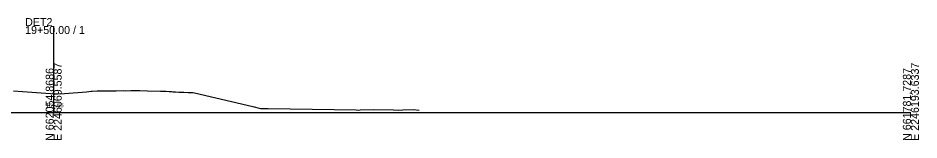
# Model space of a CAD drawing. Extents: x -26 to 603, y -10 to 9526.
# Drawn here: x 287.5 to 602.8, y 2490.3 to 2533.2 of the extents above; entities that cross this region are included whole.
import ezdxf

# ---------------------------------------------------------------- set-up
doc = ezdxf.new("R2010")
doc.units = 0
for name, color, linetype in [('Exist Cross Section Cell', 7, 'Continuous'), ('Exist XS Center Line Elevation Label', 7, 'Continuous'), ('Exist XS Ground Line', 7, 'Continuous')]:
    doc.layers.add(name, color=color, linetype=linetype)

msp = doc.modelspace()

# ---------------------------------------------------------------- linework, layer by layer
at = {"layer": 'Exist Cross Section Cell'}
for p, q in [((300, 2500), (300, 2530.33)), ((0, 2500), (300, 2500)), ((300, 2500), (600, 2500))]:
    msp.add_line(p, q, dxfattribs=at)
at = {"layer": 'Exist XS Ground Line'}
for p, q in [((285.9, 2507.53), (289.13, 2507.37)), ((289.13, 2507.37), (298.91, 2506.61)), ((303.8, 2506.67), (311.48, 2507.28)), ((311.48, 2507.28), (313.11, 2507.44)), ((313.11, 2507.44), (313.51, 2507.49)), ((313.51, 2507.49), (315.26, 2507.55)), ((315.26, 2507.55), (315.68, 2507.56)), ((315.68, 2507.56), (316.33, 2507.57)), ((316.33, 2507.57), (319.12, 2507.59)), ((319.12, 2507.59), (321.82, 2507.61)), ((321.82, 2507.61), (324.44, 2507.66)), ((324.44, 2507.66), (325.25, 2507.64)), ((325.25, 2507.64), (326.98, 2507.72)), ((326.98, 2507.72), (327.6, 2507.69)), ((327.6, 2507.69), (330.19, 2507.66)), ((330.19, 2507.66), (332.81, 2507.59)), ((332.81, 2507.59), (337.34, 2507.47)), ((337.34, 2507.47), (338.15, 2507.44)), ((338.15, 2507.44), (339.2, 2507.41)), ((339.2, 2507.41), (340.36, 2507.37)), ((340.36, 2507.37), (340.86, 2507.36)), ((340.86, 2507.36), (341.23, 2507.36)), ((341.23, 2507.36), (341.66, 2507.27)), ((341.66, 2507.27), (342.59, 2507.21)), ((342.59, 2507.21), (343.79, 2507.15)), ((343.79, 2507.15), (345.55, 2507.08)), ((345.55, 2507.08), (347.07, 2507.03)), ((347.07, 2507.03), (347.59, 2507.01)), ((347.59, 2507.01), (348.68, 2506.97)), ((348.68, 2506.97), (349.31, 2506.91)), ((349.31, 2506.91), (369.75, 2502.06)), ((298.91, 2506.61), (300, 2506.55)), ((300, 2506.55), (301.12, 2506.49)), ((301.12, 2506.49), (303.8, 2506.67)), ((369.75, 2502.06), (372.4, 2501.41)), ((372.4, 2501.41), (373.37, 2501.39)), ((373.37, 2501.39), (375.1, 2501.4)), ((375.1, 2501.4), (405.88, 2500.95)), ((405.88, 2500.95), (406.63, 2500.8)), ((406.63, 2500.8), (407.31, 2500.87)), ((407.31, 2500.87), (412.09, 2501.03)), ((412.09, 2501.03), (418.91, 2500.92)), ((418.91, 2500.92), (420.74, 2500.76)), ((420.74, 2500.76), (422.22, 2500.93)), ((422.22, 2500.93), (425.9, 2500.98)), ((425.9, 2500.98), (427.97, 2500.81))]:
    msp.add_line(p, q, dxfattribs=at)

# ---------------------------------------------------------------- texts
at = {"layer": 'Exist Cross Section Cell'}
for s, p in [('DET2', (290, 2530.33)), ('19+50.00 / 1', (290, 2527.53))]:
    msp.add_text(s, height=2.8, dxfattribs=at).set_placement(p)
for s, p in [('E 2246069.5587', (302.8, 2490)), ('E 2246193.6337', (602.8, 2490)), ('N 662054.8686', (300, 2490)), ('N 661781.7287', (600, 2490))]:
    msp.add_text(s, height=2.8, rotation=90, dxfattribs=at).set_placement(p)
at = {"layer": 'Exist XS Center Line Elevation Label'}
msp.add_text('151.55', height=1.5, dxfattribs=at).set_placement((297.16, 2501.8))

doc.saveas('drawing.dxf')
